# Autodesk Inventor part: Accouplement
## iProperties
Shininess: 64.0
Length Units: 11269
Angle Units: 11279
Time Units: 11290
Mass Units: 11283
Length Display Precision: 3
Angle Display Precision: 2
Compacted: True
Part Number: Accouplement
Document SubType Name: Modeling
Created: 2003-05
Material: Delrin - Noir
Designer: Philippe
Density: 0.0
Volumn: 0.0
Area: 0.0
PropertySet Name: Model Information
Control State: 0
Master: False
Checked Out: False
Author: Philippe
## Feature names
1. Extrusion1
2. Extrusion2
3. Extrusion3
4. Extrusion4
5. Extrusion5
6. Réseau circulaire1 [Circular Pattern]
7. Chanfrein1 [Chamfer]
8. Extrusion6
